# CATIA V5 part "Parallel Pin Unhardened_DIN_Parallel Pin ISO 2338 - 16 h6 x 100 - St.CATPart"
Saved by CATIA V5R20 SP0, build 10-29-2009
Part number: Parallel Pin Unhardened_DIN_Parallel Pin ISO 2338 - 16 h6 x 100 - St
Revision: ANY
Definition: UNKNOWN
Nomenclature: Parallel Pin Unhardened_DIN_Parallel Pin ISO 2338 - 16 h6 x 100 - St
Source: Unknown
Bounding box of the stored display mesh (mm): x 0 to 100, y -8 to 8, z -8 to 8
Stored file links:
  C:\Users\Utente\Desktop\IO LAVORO\3D X SITO CF\CUMSA\3D files SD\SD 4528\Parallel Pin Unhardened_DIN_Parallel Pin ISO 2338 - 16 h6 x 100 - St.CATPart
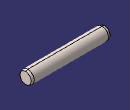
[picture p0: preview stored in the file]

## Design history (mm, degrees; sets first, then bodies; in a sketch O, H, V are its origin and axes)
Body1 "Base-Revolve" (main body)
  Solid1: solid without history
